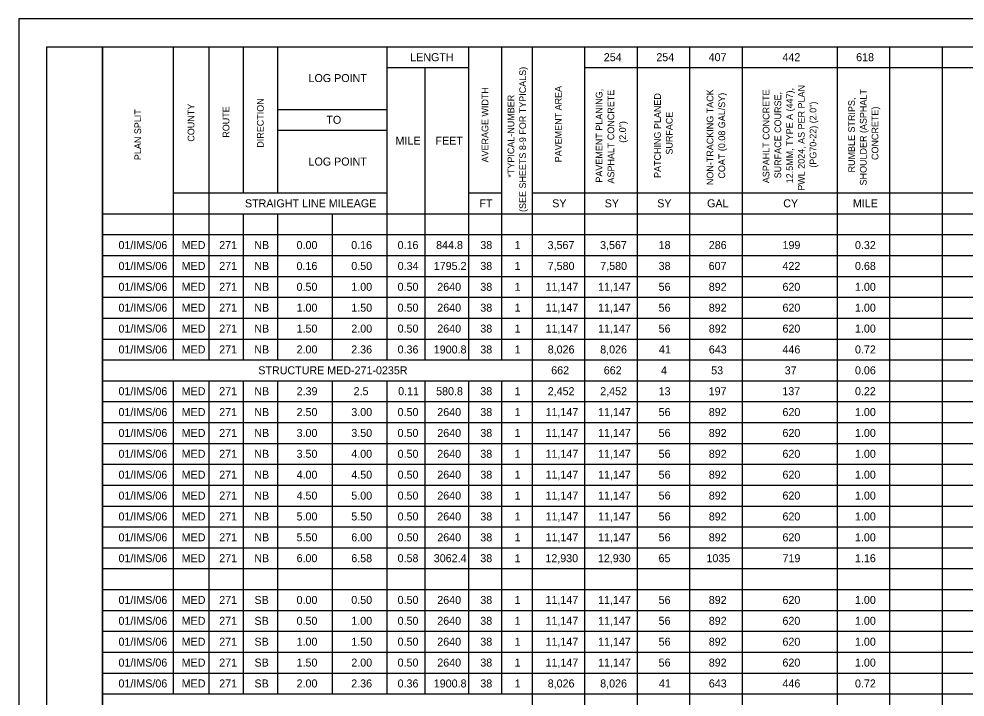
# Model space of a CAD drawing. Extents: x 0 to 34, y 0 to 22.
# Drawn here: x 0 to 17, y 9.82 to 22 of the extents above; entities that cross this region are included whole.
import ezdxf

# ---------------------------------------------------------------- set-up
doc = ezdxf.new("R2010")
doc.units = 0
for name, color, linetype in [('SH_Border', 7, 'Continuous'), ('SH_Cut_Line', 7, 'Continuous'), ('SH_Text', 7, 'Continuous')]:
    doc.layers.add(name, color=color, linetype=linetype)

msp = doc.modelspace()

# ---------------------------------------------------------------- linework, layer by layer
at = {"layer": 'SH_Border'}
for points in [[(0.5, 21.5), (1.5, 21.5), (1.5, 0.5), (0.5, 0.5)], [(1.5, 21.5), (33.5, 21.5), (33.5, 0.5), (1.5, 0.5)]]:
    msp.add_lwpolyline(points, close=True, dxfattribs=at)
at = {"layer": 'SH_Cut_Line'}
msp.add_lwpolyline([(0, 0), (34, 0), (34, 22), (0, 22)], close=True, dxfattribs=at)
at = {"layer": 'SH_Text'}
for p, q in [((1.5, 21.5), (32, 21.5)), ((1.5, 21.5), (1.5, 0.5)), ((2.771, 21.5), (2.771, 15.875)), ((3.414, 21.5), (3.414, 15.875)), ((4.03, 21.5), (4.03, 18.875)), ((4.646, 21.5), (4.646, 18.875)), ((6.612, 21.5), (6.612, 15.875)), ((8.08, 21.5), (8.08, 15.875)), ((8.67, 21.5), (8.67, 15.875)), ((9.22, 21.5), (9.22, 0.5)), ((10.164, 21.5), (10.164, 0.5)), ((11.107, 21.5), (11.107, 0.5)), ((12.051, 21.5), (12.051, 0.5)), ((12.995, 21.5), (12.995, 0.5)), ((14.699, 21.5), (14.699, 0.5)), ((15.642, 21.5), (15.642, 0.5)), ((16.586, 21.5), (16.586, 0.5)), ((6.612, 21.125), (8.08, 21.125)), ((7.293, 21.125), (7.293, 15.875)), ((10.164, 21.125), (26.023, 21.125)), ((4.646, 20.375), (6.612, 20.375)), ((4.646, 20), (6.612, 20)), ((2.771, 18.875), (6.612, 18.875)), ((8.08, 18.875), (8.67, 18.875)), ((9.22, 18.875), (32, 18.875)), ((1.5, 18.5), (32, 18.5)), ((4.03, 18.5), (4.03, 15.875)), ((4.646, 18.5), (4.646, 15.875)), ((5.629, 18.5), (5.629, 15.875)), ((1.5, 18.125), (32, 18.125)), ((1.5, 17.75), (32, 17.75)), ((1.5, 17.375), (32, 17.375)), ((1.5, 17), (32, 17)), ((1.5, 16.625), (32, 16.625)), ((1.5, 16.25), (32, 16.25)), ((1.5, 15.875), (32, 15.875)), ((1.5, 15.5), (32, 15.5)), ((2.771, 15.5), (2.771, 9.875)), ((3.414, 15.5), (3.414, 9.875)), ((4.03, 15.5), (4.03, 9.875)), ((4.646, 15.5), (4.646, 9.875)), ((5.629, 15.5), (5.629, 9.875)), ((6.612, 15.5), (6.612, 9.875)), ((7.293, 15.5), (7.293, 9.875)), ((8.08, 15.5), (8.08, 9.875)), ((8.67, 15.5), (8.67, 9.875)), ((1.5, 15.125), (32, 15.125)), ((1.5, 14.75), (32, 14.75)), ((1.5, 14.375), (32, 14.375)), ((1.5, 14), (32, 14)), ((1.5, 13.625), (32, 13.625)), ((1.5, 13.25), (32, 13.25)), ((1.5, 12.875), (32, 12.875)), ((1.5, 12.5), (32, 12.5)), ((1.5, 12.125), (32, 12.125)), ((1.5, 11.75), (32, 11.75)), ((1.5, 11.375), (32, 11.375)), ((1.5, 11), (32, 11)), ((1.5, 10.625), (32, 10.625)), ((1.5, 10.25), (32, 10.25)), ((1.5, 9.875), (32, 9.875))]:
    msp.add_line(p, q, dxfattribs=at)

# ---------------------------------------------------------------- texts
for s, height, p in [('LENGTH', 0.1438, (7.031, 21.241)), ('254', 0.1438, (10.509, 21.241)), ('254', 0.1438, (11.453, 21.241)), ('407', 0.1438, (12.393, 21.241)), ('442', 0.1438, (13.719, 21.241)), ('618', 0.1438, (15.043, 21.241)), ('LOG POINT', 0.1438, (5.204, 20.866)), ('TO', 0.1438, (5.524, 20.116)), ('MILE', 0.1438, (6.767, 19.741)), ('FEET', 0.1438, (7.485, 19.741)), ('LOG POINT', 0.1438, (5.204, 19.366)), ('STRAIGHT LINE MILEAGE', 0.14375, (4.061, 18.616)), ('FT', 0.1438, (8.275, 18.616)), ('SY', 0.1438, (9.582, 18.616)), ('SY', 0.1438, (10.525, 18.616)), ('SY', 0.1438, (11.469, 18.616)), ('GAL', 0.1438, (12.365, 18.616)), ('CY', 0.1438, (13.733, 18.616)), ('MILE', 0.1438, (14.985, 18.616)), ('01/IMS/06', 0.1438, (1.789, 17.866)), ('MED', 0.1438, (2.924, 17.866)), ('271', 0.1438, (3.599, 17.866)), ('NB', 0.1438, (4.229, 17.866)), ('0.00', 0.1438, (4.989, 17.866)), ('0.16', 0.1438, (5.971, 17.866)), ('0.16', 0.1438, (6.804, 17.866)), ('844.8', 0.1438, (7.496, 17.866)), ('38', 0.1438, (8.29, 17.866)), ('1', 0.144, (8.906, 17.866)), ('3,567', 0.1438, (9.499, 17.866)), ('3,567', 0.1438, (10.442, 17.866)), ('18', 0.1438, (11.494, 17.866)), ('286', 0.1438, (12.395, 17.866)), ('199', 0.1438, (13.72, 17.866)), ('0.32', 0.1438, (15.022, 17.866)), ('01/IMS/06', 0.1438, (1.789, 17.491)), ('MED', 0.1438, (2.924, 17.491)), ('271', 0.1438, (3.599, 17.491)), ('NB', 0.1438, (4.229, 17.491)), ('0.16', 0.1438, (4.988, 17.491)), ('0.50', 0.1438, (5.972, 17.491)), ('0.34', 0.1438, (6.805, 17.491)), ('1795.2', 0.1438, (7.454, 17.491)), ('38', 0.1438, (8.29, 17.491)), ('1', 0.144, (8.906, 17.491)), ('7,580', 0.1438, (9.501, 17.491)), ('7,580', 0.1438, (10.445, 17.491)), ('38', 0.1438, (11.494, 17.491)), ('607', 0.1438, (12.393, 17.491)), ('422', 0.1438, (13.719, 17.491)), ('0.68', 0.1438, (15.022, 17.491)), ('01/IMS/06', 0.1438, (1.789, 17.116)), ('MED', 0.1438, (2.924, 17.116)), ('271', 0.1438, (3.599, 17.116)), ('NB', 0.1438, (4.229, 17.116)), ('0.50', 0.1438, (4.989, 17.116)), ('1.00', 0.1438, (5.972, 17.116)), ('0.50', 0.1438, (6.804, 17.116)), ('2640', 0.1438, (7.517, 17.116)), ('38', 0.1438, (8.29, 17.116)), ('1', 0.144, (8.906, 17.116)), ('11,147', 0.1438, (9.462, 17.116)), ('11,147', 0.1438, (10.406, 17.116)), ('56', 0.1438, (11.494, 17.116)), ('892', 0.1438, (12.395, 17.116)), ('620', 0.1438, (13.719, 17.116)), ('1.00', 0.1438, (15.022, 17.116)), ('01/IMS/06', 0.1438, (1.789, 16.741)), ('MED', 0.1438, (2.924, 16.741)), ('271', 0.1438, (3.599, 16.741)), ('NB', 0.1438, (4.229, 16.741)), ('1.00', 0.1438, (4.989, 16.741)), ('1.50', 0.1438, (5.972, 16.741)), ('0.50', 0.1438, (6.804, 16.741)), ('2640', 0.1438, (7.517, 16.741)), ('38', 0.1438, (8.29, 16.741)), ('1', 0.144, (8.906, 16.741)), ('11,147', 0.1438, (9.462, 16.741)), ('11,147', 0.1438, (10.406, 16.741)), ('56', 0.1438, (11.494, 16.741)), ('892', 0.1438, (12.395, 16.741)), ('620', 0.1438, (13.719, 16.741)), ('1.00', 0.1438, (15.022, 16.741)), ('01/IMS/06', 0.1438, (1.789, 16.366)), ('MED', 0.1438, (2.924, 16.366)), ('271', 0.1438, (3.599, 16.366)), ('NB', 0.1438, (4.229, 16.366)), ('1.50', 0.1438, (4.989, 16.366)), ('2.00', 0.1438, (5.972, 16.366)), ('0.50', 0.1438, (6.804, 16.366)), ('2640', 0.1438, (7.517, 16.366)), ('38', 0.1438, (8.29, 16.366)), ('1', 0.144, (8.906, 16.366)), ('11,147', 0.1438, (9.462, 16.366)), ('11,147', 0.1438, (10.406, 16.366)), ('56', 0.1438, (11.494, 16.366)), ('892', 0.1438, (12.395, 16.366)), ('620', 0.1438, (13.719, 16.366)), ('1.00', 0.1438, (15.022, 16.366)), ('01/IMS/06', 0.1438, (1.789, 15.991)), ('MED', 0.1438, (2.924, 15.991)), ('271', 0.1438, (3.599, 15.991)), ('NB', 0.1438, (4.229, 15.991)), ('2.00', 0.1438, (4.989, 15.991)), ('2.36', 0.1438, (5.971, 15.991)), ('0.36', 0.1438, (6.804, 15.991)), ('1900.8', 0.1438, (7.454, 15.991)), ('38', 0.1438, (8.29, 15.991)), ('1', 0.144, (8.906, 15.991)), ('8,026', 0.1438, (9.501, 15.991)), ('8,026', 0.1438, (10.444, 15.991)), ('41', 0.1438, (11.499, 15.991)), ('643', 0.1438, (12.396, 15.991)), ('446', 0.1438, (13.719, 15.991)), ('0.72', 0.1438, (15.022, 15.991)), ('STRUCTURE MED-271-0235R', 0.14375, (4.301, 15.616)), ('662', 0.1438, (9.564, 15.616)), ('662', 0.1438, (10.508, 15.616)), ('4', 0.144, (11.537, 15.616)), ('53', 0.1438, (12.438, 15.616)), ('37', 0.1438, (13.759, 15.616)), ('0.06', 0.1438, (15.022, 15.616)), ('01/IMS/06', 0.1438, (1.789, 15.241)), ('MED', 0.1438, (2.924, 15.241)), ('271', 0.1438, (3.599, 15.241)), ('NB', 0.1438, (4.229, 15.241)), ('2.39', 0.1438, (4.99, 15.241)), ('2.5', 0.1438, (6.013, 15.241)), ('0.11', 0.1438, (6.814, 15.241)), ('580.8', 0.1438, (7.496, 15.241)), ('38', 0.1438, (8.29, 15.241)), ('1', 0.144, (8.906, 15.241)), ('2,452', 0.1438, (9.501, 15.241)), ('2,452', 0.1438, (10.445, 15.241)), ('13', 0.1438, (11.495, 15.241)), ('197', 0.1438, (12.393, 15.241)), ('137', 0.1438, (13.717, 15.241)), ('0.22', 0.1438, (15.022, 15.241)), ('01/IMS/06', 0.1438, (1.789, 14.866)), ('MED', 0.1438, (2.924, 14.866)), ('271', 0.1438, (3.599, 14.866)), ('NB', 0.1438, (4.229, 14.866)), ('2.50', 0.1438, (4.989, 14.866)), ('3.00', 0.1438, (5.972, 14.866)), ('0.50', 0.1438, (6.804, 14.866)), ('2640', 0.1438, (7.517, 14.866)), ('38', 0.1438, (8.29, 14.866)), ('1', 0.144, (8.906, 14.866)), ('11,147', 0.1438, (9.462, 14.866)), ('11,147', 0.1438, (10.406, 14.866)), ('56', 0.1438, (11.494, 14.866)), ('892', 0.1438, (12.395, 14.866)), ('620', 0.1438, (13.719, 14.866)), ('1.00', 0.1438, (15.022, 14.866)), ('01/IMS/06', 0.1438, (1.789, 14.491)), ('MED', 0.1438, (2.924, 14.491)), ('271', 0.1438, (3.599, 14.491)), ('NB', 0.1438, (4.229, 14.491)), ('3.00', 0.1438, (4.989, 14.491)), ('3.50', 0.1438, (5.972, 14.491)), ('0.50', 0.1438, (6.804, 14.491)), ('2640', 0.1438, (7.517, 14.491)), ('38', 0.1438, (8.29, 14.491)), ('1', 0.144, (8.906, 14.491)), ('11,147', 0.1438, (9.462, 14.491)), ('11,147', 0.1438, (10.406, 14.491)), ('56', 0.1438, (11.494, 14.491)), ('892', 0.1438, (12.395, 14.491)), ('620', 0.1438, (13.719, 14.491)), ('1.00', 0.1438, (15.022, 14.491)), ('01/IMS/06', 0.1438, (1.789, 14.116)), ('MED', 0.1438, (2.924, 14.116)), ('271', 0.1438, (3.599, 14.116)), ('NB', 0.1438, (4.229, 14.116)), ('3.50', 0.1438, (4.989, 14.116)), ('4.00', 0.1438, (5.972, 14.116)), ('0.50', 0.1438, (6.804, 14.116)), ('2640', 0.1438, (7.517, 14.116)), ('38', 0.1438, (8.29, 14.116)), ('1', 0.144, (8.906, 14.116)), ('11,147', 0.1438, (9.462, 14.116)), ('11,147', 0.1438, (10.406, 14.116)), ('56', 0.1438, (11.494, 14.116)), ('892', 0.1438, (12.395, 14.116)), ('620', 0.1438, (13.719, 14.116)), ('1.00', 0.1438, (15.022, 14.116)), ('01/IMS/06', 0.1438, (1.789, 13.741)), ('MED', 0.1438, (2.924, 13.741)), ('271', 0.1438, (3.599, 13.741)), ('NB', 0.1438, (4.229, 13.741)), ('4.00', 0.1438, (4.989, 13.741)), ('4.50', 0.1438, (5.972, 13.741)), ('0.50', 0.1438, (6.804, 13.741)), ('2640', 0.1438, (7.517, 13.741)), ('38', 0.1438, (8.29, 13.741)), ('1', 0.144, (8.906, 13.741)), ('11,147', 0.1438, (9.462, 13.741)), ('11,147', 0.1438, (10.406, 13.741)), ('56', 0.1438, (11.494, 13.741)), ('892', 0.1438, (12.395, 13.741)), ('620', 0.1438, (13.719, 13.741)), ('1.00', 0.1438, (15.022, 13.741)), ('01/IMS/06', 0.1438, (1.789, 13.366)), ('MED', 0.1438, (2.924, 13.366)), ('271', 0.1438, (3.599, 13.366)), ('NB', 0.1438, (4.229, 13.366)), ('4.50', 0.1438, (4.989, 13.366)), ('5.00', 0.1438, (5.972, 13.366)), ('0.50', 0.1438, (6.804, 13.366)), ('2640', 0.1438, (7.517, 13.366)), ('38', 0.1438, (8.29, 13.366)), ('1', 0.144, (8.906, 13.366)), ('11,147', 0.1438, (9.462, 13.366)), ('11,147', 0.1438, (10.406, 13.366)), ('56', 0.1438, (11.494, 13.366)), ('892', 0.1438, (12.395, 13.366)), ('620', 0.1438, (13.719, 13.366)), ('1.00', 0.1438, (15.022, 13.366)), ('01/IMS/06', 0.1438, (1.789, 12.991)), ('MED', 0.1438, (2.924, 12.991)), ('271', 0.1438, (3.599, 12.991)), ('NB', 0.1438, (4.229, 12.991)), ('5.00', 0.1438, (4.989, 12.991)), ('5.50', 0.1438, (5.972, 12.991)), ('0.50', 0.1438, (6.804, 12.991)), ('2640', 0.1438, (7.517, 12.991)), ('38', 0.1438, (8.29, 12.991)), ('1', 0.144, (8.906, 12.991)), ('11,147', 0.1438, (9.462, 12.991)), ('11,147', 0.1438, (10.406, 12.991)), ('56', 0.1438, (11.494, 12.991)), ('892', 0.1438, (12.395, 12.991)), ('620', 0.1438, (13.719, 12.991)), ('1.00', 0.1438, (15.022, 12.991)), ('01/IMS/06', 0.1438, (1.789, 12.616)), ('MED', 0.1438, (2.924, 12.616)), ('271', 0.1438, (3.599, 12.616)), ('NB', 0.1438, (4.229, 12.616)), ('5.50', 0.1438, (4.989, 12.616)), ('6.00', 0.1438, (5.972, 12.616)), ('0.50', 0.1438, (6.804, 12.616)), ('2640', 0.1438, (7.517, 12.616)), ('38', 0.1438, (8.29, 12.616)), ('1', 0.144, (8.906, 12.616)), ('11,147', 0.1438, (9.462, 12.616)), ('11,147', 0.1438, (10.406, 12.616)), ('56', 0.1438, (11.494, 12.616)), ('892', 0.1438, (12.395, 12.616)), ('620', 0.1438, (13.719, 12.616)), ('1.00', 0.1438, (15.022, 12.616)), ('01/IMS/06', 0.1438, (1.789, 12.241)), ('MED', 0.1438, (2.924, 12.241)), ('271', 0.1438, (3.599, 12.241)), ('NB', 0.1438, (4.229, 12.241)), ('6.00', 0.1438, (4.989, 12.241)), ('6.58', 0.1438, (5.972, 12.241)), ('0.58', 0.1438, (6.804, 12.241)), ('3062.4', 0.1438, (7.454, 12.241)), ('38', 0.1438, (8.29, 12.241)), ('1', 0.144, (8.906, 12.241)), ('12,930', 0.1438, (9.459, 12.241)), ('12,930', 0.1438, (10.403, 12.241)), ('65', 0.1438, (11.493, 12.241)), ('1035', 0.1438, (12.353, 12.241)), ('719', 0.1438, (13.72, 12.241)), ('1.16', 0.1438, (15.022, 12.241)), ('01/IMS/06', 0.1438, (1.789, 11.491)), ('MED', 0.1438, (2.924, 11.491)), ('271', 0.1438, (3.599, 11.491)), ('SB', 0.1438, (4.233, 11.491)), ('0.00', 0.1438, (4.989, 11.491)), ('0.50', 0.1438, (5.972, 11.491)), ('0.50', 0.1438, (6.804, 11.491)), ('2640', 0.1438, (7.517, 11.491)), ('38', 0.1438, (8.29, 11.491)), ('1', 0.144, (8.906, 11.491)), ('11,147', 0.1438, (9.462, 11.491)), ('11,147', 0.1438, (10.406, 11.491)), ('56', 0.1438, (11.494, 11.491)), ('892', 0.1438, (12.395, 11.491)), ('620', 0.1438, (13.719, 11.491)), ('1.00', 0.1438, (15.022, 11.491)), ('01/IMS/06', 0.1438, (1.789, 11.116)), ('MED', 0.1438, (2.924, 11.116)), ('271', 0.1438, (3.599, 11.116)), ('SB', 0.1438, (4.233, 11.116)), ('0.50', 0.1438, (4.989, 11.116)), ('1.00', 0.1438, (5.972, 11.116)), ('0.50', 0.1438, (6.804, 11.116)), ('2640', 0.1438, (7.517, 11.116)), ('38', 0.1438, (8.29, 11.116)), ('1', 0.144, (8.906, 11.116)), ('11,147', 0.1438, (9.462, 11.116)), ('11,147', 0.1438, (10.406, 11.116)), ('56', 0.1438, (11.494, 11.116)), ('892', 0.1438, (12.395, 11.116)), ('620', 0.1438, (13.719, 11.116)), ('1.00', 0.1438, (15.022, 11.116)), ('01/IMS/06', 0.1438, (1.789, 10.741)), ('MED', 0.1438, (2.924, 10.741)), ('271', 0.1438, (3.599, 10.741)), ('SB', 0.1438, (4.233, 10.741)), ('1.00', 0.1438, (4.989, 10.741)), ('1.50', 0.1438, (5.972, 10.741)), ('0.50', 0.1438, (6.804, 10.741)), ('2640', 0.1438, (7.517, 10.741)), ('38', 0.1438, (8.29, 10.741)), ('1', 0.144, (8.906, 10.741)), ('11,147', 0.1438, (9.462, 10.741)), ('11,147', 0.1438, (10.406, 10.741)), ('56', 0.1438, (11.494, 10.741)), ('892', 0.1438, (12.395, 10.741)), ('620', 0.1438, (13.719, 10.741)), ('1.00', 0.1438, (15.022, 10.741)), ('01/IMS/06', 0.1438, (1.789, 10.366)), ('MED', 0.1438, (2.924, 10.366)), ('271', 0.1438, (3.599, 10.366)), ('SB', 0.1438, (4.233, 10.366)), ('1.50', 0.1438, (4.989, 10.366)), ('2.00', 0.1438, (5.972, 10.366)), ('0.50', 0.1438, (6.804, 10.366)), ('2640', 0.1438, (7.517, 10.366)), ('38', 0.1438, (8.29, 10.366)), ('1', 0.144, (8.906, 10.366)), ('11,147', 0.1438, (9.462, 10.366)), ('11,147', 0.1438, (10.406, 10.366)), ('56', 0.1438, (11.494, 10.366)), ('892', 0.1438, (12.395, 10.366)), ('620', 0.1438, (13.719, 10.366)), ('1.00', 0.1438, (15.022, 10.366)), ('01/IMS/06', 0.1438, (1.789, 9.991)), ('MED', 0.1438, (2.924, 9.991)), ('271', 0.1438, (3.599, 9.991)), ('SB', 0.1438, (4.233, 9.991)), ('2.00', 0.1438, (4.989, 9.991)), ('2.36', 0.1438, (5.971, 9.991)), ('0.36', 0.1438, (6.804, 9.991)), ('1900.8', 0.1438, (7.454, 9.991)), ('38', 0.1438, (8.29, 9.991)), ('1', 0.144, (8.906, 9.991)), ('8,026', 0.1438, (9.501, 9.991)), ('8,026', 0.1438, (10.444, 9.991)), ('41', 0.1438, (11.499, 9.991)), ('643', 0.1438, (12.396, 9.991)), ('446', 0.1438, (13.719, 9.991)), ('0.72', 0.1438, (15.022, 9.991))]:
    msp.add_text(s, height=height, dxfattribs=at).set_placement(p)
for s, height, p in [('(SEE SHEETS 8-9 FOR TYPICALS)', 0.12058, (9.111, 18.532)), ('AVERAGE WIDTH', 0.12058, (8.435, 19.422)), ('PAVEMENT AREA', 0.12058, (9.752, 19.425)), ('12.5MM, TYPE A (447), ', 0.12058, (13.907, 19.048)), ('PWL 2024, AS PER PLAN ', 0.12058, (14.118, 18.913)), ('*TYPICAL-NUMBER                                     ', 0.12058, (8.9, 19.15)), ('PAVEMENT PLANING, ', 0.12058, (10.485, 19.06)), ('ASPHALT CONCRETE ', 0.12058, (10.696, 19.043)), ('PATCHING PLANED ', 0.12058, (11.534, 19.144)), ('NON-TRACKING TACK ', 0.12058, (12.478, 19.015)), ('COAT (0.08 GAL/SY)', 0.12058, (12.689, 19.132)), ('ASPAHLT CONCRETE ', 0.12058, (13.485, 19.049)), ('SURFACE COURSE, ', 0.12058, (13.696, 19.137)), ('RUMBLE STRIPS, ', 0.12058, (15.02, 19.243)), ('SHOULDER (ASPHALT ', 0.12058, (15.231, 19.009)), ('COUNTY', 0.1206, (3.153, 19.795)), ('ROUTE', 0.1206, (3.782, 19.866)), ('DIRECTION', 0.1206, (4.398, 19.687)), ('(PG70-22) (2.0")', 0.12058, (14.329, 19.328)), ('CONCRETE)', 0.1206, (15.442, 19.466)), ('PLAN SPLIT', 0.1206, (2.196, 19.464)), ('SURFACE', 0.1206, (11.745, 19.563)), ('(2.0")', 0.1206, (10.907, 19.775))]:
    msp.add_text(s, height=height, rotation=90, dxfattribs=at).set_placement(p)

doc.saveas('drawing.dxf')
